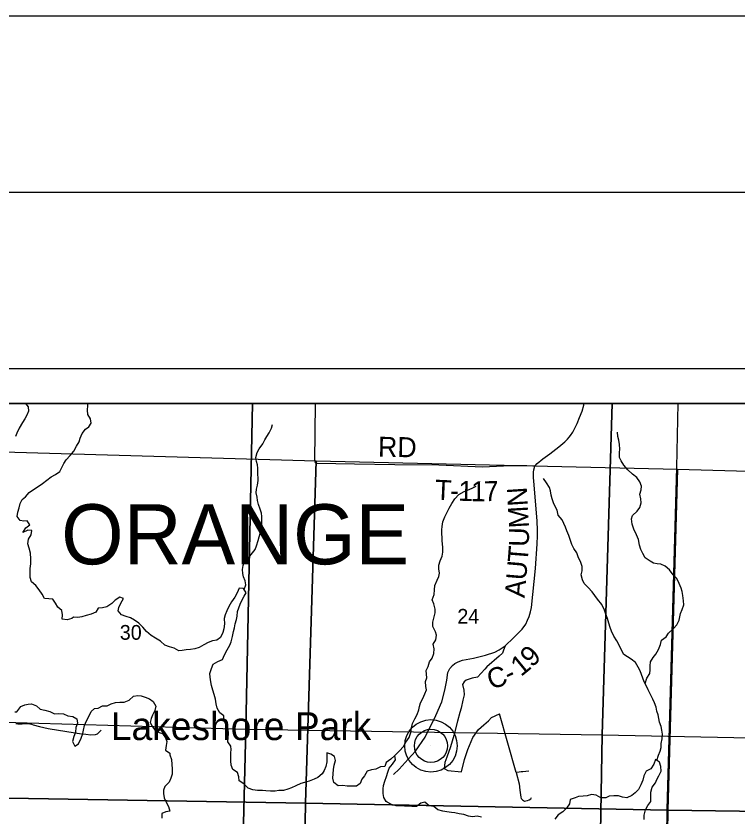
# Model space of a CAD drawing. Extents: x -19.9 to 41.9, y 0 to 32.3.
# Drawn here: x 5.266 to 7.317, y 19.727 to 22 of the extents above; entities that cross this region are included whole.
import ezdxf

# ---------------------------------------------------------------- set-up
doc = ezdxf.new("R2010")
doc.units = 0
for name, color, linetype in [('GM_X_Corporation', 7, 'Continuous'), ('GM_X_County_Road', 7, 'Continuous'), ('GM_X_County_Road_Text', 7, 'Continuous'), ('GM_X_Major_Lake', 7, 'Continuous'), ('GM_X_Minor_River', 7, 'Continuous'), ('GM_X_Section', 7, 'Continuous'), ('GM_X_Section_Text', 7, 'Continuous'), ('GM_X_Township', 7, 'Continuous'), ('GM_X_Township_Road', 7, 'Continuous'), ('GM_X_Township_Road_Text', 7, 'Continuous'), ('GM_X_Township_Text', 7, 'Continuous'), ('GM_X_Unincorporated', 7, 'Continuous'), ('GM_X_Unincorporated_Location', 7, 'Continuous'), ('GM_X_Unincorporated_Text', 7, 'Continuous'), ('SH_Border', 7, 'Continuous'), ('SH_Cut_Line', 7, 'Continuous'), ('SH_Data', 7, 'Continuous')]:
    doc.layers.add(name, color=color, linetype=linetype)

msp = doc.modelspace()

# ---------------------------------------------------------------- linework, layer by layer
at = {"layer": 'GM_X_Corporation'}
for points in [[(8.9, 17.8974), (8.9, 20.9), (2.1, 20.9), (2.1, 17.918), (2.4715, 17.9106), (2.973, 17.9007), (3.7505, 17.884), (3.984, 17.879), (4.2613, 17.8672), (4.9169, 17.8392), (5.0192, 17.8403), (5.0257, 17.9637), (5.4954, 17.9559), (5.761, 17.9543), (5.9048, 17.9534), (6.2397, 17.9517), (6.2497, 17.9517), (6.3069, 17.9505), (6.7, 17.9422), (6.9468, 17.937), (7.3858, 17.9277), (7.5529, 17.9242), (7.9072, 17.9171)], [(5.9372, 20.9), (5.0886, 20.9), (5.0885, 20.8933), (5.0685, 20), (5.9183, 19.976)], [(6.9594, 20.9), (5.9372, 20.9), (5.9183, 19.976), (6.9305, 19.9596)], [(7.9862, 20.9), (6.9594, 20.9), (6.9305, 19.9596), (7.9591, 19.9393)], [(5.0685, 20), (5.9183, 19.976), (5.8941, 18.9811), (5.0551, 18.9965), (5.0703, 19.9026)], [(5.9183, 19.976), (6.9305, 19.9596), (6.9135, 18.9637), (5.8941, 18.9811)], [(7.9591, 19.9393), (7.944, 18.9426), (6.9135, 18.9637), (6.9305, 19.9596)]]:
    msp.add_lwpolyline(points, close=True, dxfattribs=at)
msp.add_lwpolyline([(2.973, 17.9007), (3.7505, 17.884), (3.984, 17.879), (4.2613, 17.8672), (4.9169, 17.8392), (5.0192, 17.8403), (5.0257, 17.9637), (5.4954, 17.9559), (5.761, 17.9543), (5.9048, 17.9534), (6.2397, 17.9517), (6.2497, 17.9517), (6.3069, 17.9505), (6.7, 17.9422), (6.9468, 17.937), (7.3858, 17.9277), (7.5529, 17.9242), (7.9072, 17.9171), (7.9208, 18.3004), (7.9387, 18.9418), (7.9433, 19.1981), (7.9567, 19.9408), (7.9833, 20.9), (2.1, 20.9)], dxfattribs=at)
at = {"layer": 'GM_X_County_Road'}
msp.add_lwpolyline([(6.3377, 19.8473), (6.3538, 19.8624), (6.38, 19.891), (6.401, 19.9134), (6.4282, 19.9531), (6.4584, 20.0142), (6.4757, 20.053), (6.4844, 20.0865), (6.4893, 20.1146), (6.4921, 20.1368), (6.4982, 20.148), (6.5055, 20.157), (6.5124, 20.1627), (6.5214, 20.1674), (6.534, 20.1714), (6.565, 20.177), (6.5993, 20.1859), (6.6261, 20.1947), (6.6385, 20.2011), (6.6466, 20.2068), (6.6551, 20.2126), (6.6791, 20.235), (6.7039, 20.2596), (6.714, 20.2739), (6.719, 20.2853), (6.7234, 20.296), (6.7274, 20.3087), (6.7304, 20.3216), (6.7414, 20.4315), (6.7458, 20.5016), (6.7474, 20.5248), (6.7469, 20.5411), (6.7464, 20.5661), (6.7377, 20.6691), (6.7359, 20.6902), (6.7357, 20.7051), (6.7369, 20.7118), (6.7382, 20.7189), (6.7394, 20.7228), (6.7462, 20.7302), (6.7623, 20.7431), (6.7826, 20.7572), (6.8082, 20.7775), (6.8244, 20.7918), (6.832, 20.7991), (6.837, 20.8048), (6.8409, 20.8095), (6.8477, 20.8185), (6.8534, 20.8305), (6.8594, 20.843), (6.8664, 20.86), (6.8739, 20.8784), (6.8788, 20.8957), (6.8798, 20.9)], dxfattribs=at)
at = {"layer": 'GM_X_Major_Lake'}
for points in [[(5.2926, 20.9), (5.3008, 20.8907), (5.3018, 20.8789), (5.2963, 20.8667), (5.2911, 20.8568), (5.2841, 20.846), (5.2749, 20.8299), (5.2679, 20.8162), (5.2642, 20.8062)], [(5.2832, 20.6279), (5.2929, 20.6356), (5.3034, 20.6476), (5.3184, 20.658), (5.3286, 20.6647), (5.3414, 20.6732), (5.3534, 20.6829), (5.3654, 20.6918), (5.3778, 20.6985), (5.3902, 20.7074), (5.395, 20.717), (5.402, 20.7303), (5.4083, 20.7403), (5.4199, 20.7526), (5.4299, 20.7653), (5.438, 20.7787), (5.4454, 20.791), (5.4483, 20.8017), (5.4538, 20.8147), (5.4635, 20.8273), (5.4732, 20.8336), (5.4795, 20.8443), (5.4774, 20.8571), (5.4696, 20.8692), (5.4686, 20.8809), (5.4699, 20.8942), (5.4698, 20.9)], [(5.4246, 20.2899), (5.4117, 20.2863), (5.3968, 20.2879), (5.3978, 20.3005), (5.3964, 20.3126), (5.3845, 20.3223), (5.3782, 20.3339), (5.3704, 20.3452), (5.359, 20.3461), (5.3468, 20.3471), (5.3398, 20.3587), (5.3316, 20.3711), (5.3219, 20.3838), (5.3095, 20.3939), (5.3059, 20.4067), (5.3057, 20.4204), (5.3066, 20.4321), (5.3079, 20.4451), (5.3084, 20.4591), (5.3074, 20.4758), (5.303, 20.4894), (5.2994, 20.5018), (5.3014, 20.5148), (5.3092, 20.527), (5.3113, 20.5396), (5.2998, 20.5409), (5.2855, 20.5342), (5.2937, 20.5472), (5.3049, 20.5558), (5.2975, 20.5674), (5.288, 20.5665), (5.2781, 20.5679), (5.2696, 20.5795), (5.2712, 20.5916), (5.2745, 20.6038), (5.2777, 20.6164), (5.2832, 20.6279)], [(5.9133, 19.8207), (5.8998, 19.8292), (5.8992, 19.841), (5.8949, 19.8531), (5.8822, 19.8616), (5.8774, 19.874), (5.8761, 19.8857), (5.8759, 19.8979), (5.8761, 19.9085), (5.8771, 19.918), (5.8761, 19.9279), (5.868, 19.9395), (5.8681, 19.9512), (5.8698, 19.9638), (5.8681, 19.9767), (5.8626, 19.988), (5.8559, 20.0011), (5.8565, 20.0136), (5.8445, 20.0226), (5.8371, 20.0357), (5.8342, 20.0478), (5.8325, 20.0607), (5.8288, 20.0739), (5.8248, 20.0863), (5.8216, 20.0999), (5.8195, 20.1098), (5.817, 20.1234), (5.8168, 20.134), (5.8211, 20.1477), (5.8263, 20.1603), (5.839, 20.1681), (5.8523, 20.1737), (5.8581, 20.1867), (5.8655, 20.2008), (5.8736, 20.2138), (5.8773, 20.2238), (5.8812, 20.239), (5.8836, 20.2527), (5.8861, 20.2637), (5.8886, 20.2744), (5.8922, 20.287), (5.8939, 20.2965), (5.8952, 20.3098), (5.8985, 20.3201), (5.9025, 20.3308), (5.9073, 20.3407), (5.9143, 20.3534), (5.9194, 20.3629), (5.9124, 20.3749), (5.8998, 20.3759), (5.894, 20.3625), (5.8877, 20.3503), (5.878, 20.3368), (5.8703, 20.3242), (5.8644, 20.3119), (5.8597, 20.3001), (5.8575, 20.2902), (5.8578, 20.275), (5.8561, 20.2602), (5.8533, 20.2499), (5.8467, 20.2362), (5.8365, 20.2288), (5.8236, 20.2267), (5.8115, 20.2219), (5.7995, 20.2149), (5.7863, 20.2075), (5.7742, 20.2035), (5.7613, 20.2018), (5.7492, 20.2008), (5.7378, 20.1991), (5.7283, 20.1986), (5.7153, 20.2055), (5.7015, 20.2095), (5.6889, 20.2142), (5.6761, 20.2254), (5.6623, 20.2339), (5.6497, 20.2413), (5.6369, 20.2528), (5.6261, 20.2652), (5.6152, 20.2764), (5.6025, 20.2856), (5.591, 20.2919), (5.5784, 20.2955), (5.5654, 20.3006), (5.5565, 20.3114), (5.5578, 20.3209), (5.5637, 20.3339), (5.5711, 20.347), (5.5612, 20.3506), (5.5476, 20.342), (5.5379, 20.3327), (5.524, 20.3234), (5.5115, 20.3206), (5.4997, 20.3196), (5.4923, 20.3081), (5.4795, 20.3018), (5.4655, 20.2989), (5.4526, 20.2949), (5.4412, 20.2928), (5.429, 20.2942), (5.4246, 20.2899)], [(5.2624, 20.0255), (5.2682, 20.0252), (5.2797, 20.0398), (5.2914, 20.0449), (5.3009, 20.0466), (5.3104, 20.0475), (5.3238, 20.0421), (5.3346, 20.0324), (5.3483, 20.0296), (5.3617, 20.0256), (5.3751, 20.0198), (5.3876, 20.02), (5.4009, 20.019), (5.4132, 20.0136), (5.4269, 20.0115), (5.4388, 20.0052), (5.4409, 19.9931), (5.4362, 19.9802), (5.4345, 19.9676), (5.4305, 19.9547), (5.4266, 19.9409), (5.4329, 19.9278), (5.4434, 19.9344), (5.4511, 19.9504), (5.4562, 19.9638), (5.458, 19.9733), (5.4608, 19.9859), (5.4659, 19.9996), (5.4725, 20.0119), (5.4791, 20.0264), (5.4889, 20.0341), (5.4991, 20.0355), (5.5116, 20.0421), (5.5249, 20.0423), (5.5365, 20.0482), (5.5487, 20.0518), (5.5604, 20.0524), (5.5734, 20.0522), (5.5873, 20.0585), (5.5997, 20.0697), (5.6118, 20.0711), (5.6213, 20.0701), (5.6332, 20.0665), (5.645, 20.0621), (5.6551, 20.054), (5.6629, 20.0416), (5.66, 20.0286), (5.6538, 20.016), (5.6494, 20.0061), (5.6469, 19.9946), (5.6528, 19.9841)], [(5.6528, 19.9841), (5.661, 19.9725), (5.6721, 19.9666), (5.6817, 19.9637), (5.6906, 19.951), (5.6942, 19.9412), (5.6921, 19.9298), (5.6904, 19.9164), (5.7024, 19.9075)], [(5.7024, 19.9075), (5.7032, 19.9026), (5.7072, 19.8898), (5.709, 19.8754), (5.7096, 19.8629), (5.7094, 19.8485), (5.7058, 19.8367), (5.7007, 19.8252), (5.6883, 19.8132), (5.6847, 19.8029), (5.6853, 19.7934), (5.687, 19.7806), (5.6921, 19.7689), (5.6992, 19.7561), (5.7032, 19.7433), (5.6911, 19.7412), (5.6801, 19.7361), (5.6803, 19.7232)], [(6.3175, 19.7702), (6.3108, 19.7822), (6.3087, 19.7931), (6.3089, 19.8068), (6.3098, 19.8163), (6.3138, 19.8285), (6.3182, 19.8415), (6.3225, 19.8541), (6.3258, 19.8655), (6.3354, 19.8767), (6.344, 19.8886), (6.3423, 19.9011), (6.3306, 19.891), (6.3175, 19.8813), (6.3139, 19.8702), (6.301, 19.8685), (6.2882, 19.8626), (6.276, 19.8605), (6.2635, 19.8569), (6.2562, 19.8431), (6.248, 19.8335), (6.2436, 19.822), (6.2327, 19.8143), (6.2202, 19.8137), (6.2061, 19.8142), (6.1943, 19.8155), (6.1814, 19.8153), (6.1687, 19.8242), (6.1658, 19.8367), (6.1664, 19.8488), (6.168, 19.8618), (6.1701, 19.8739), (6.173, 19.8869), (6.1709, 19.8982), (6.1597, 19.9045), (6.149, 19.9089), (6.1485, 19.8956), (6.1487, 19.8827), (6.1455, 19.8697), (6.1411, 19.859), (6.1352, 19.8491), (6.1236, 19.8383), (6.1126, 19.8339), (6.099, 19.8287), (6.085, 19.824), (6.0752, 19.8215), (6.0612, 19.8148), (6.048, 19.8093), (6.0382, 19.8057), (6.0253, 19.8021), (6.012, 19.8015), (6.0022, 19.8002), (5.9885, 19.8), (5.9759, 19.8009), (5.9664, 19.8015), (5.952, 19.8016), (5.939, 19.8033), (5.9256, 19.8088), (5.9133, 19.8207)], [(7.0497, 19.7194), (7.0499, 19.7319), (7.0538, 19.7468), (7.0608, 19.759), (7.0694, 19.7709), (7.0692, 19.7846), (7.0686, 19.7975), (7.0733, 19.8108), (7.0822, 19.8239), (7.0862, 19.8334), (7.0914, 19.843), (7.0984, 19.8568), (7.0978, 19.8697), (7.0934, 19.8825), (7.0826, 19.8895), (7.0779, 19.8765), (7.0686, 19.8635), (7.0562, 19.8565), (7.0488, 19.8434), (7.046, 19.8309), (7.0405, 19.8175), (7.0338, 19.8049), (7.0245, 19.7948), (7.0147, 19.7875), (7.0012, 19.7812), (6.989, 19.7829), (6.9775, 19.7869), (6.9638, 19.787), (6.9509, 19.7853), (6.9411, 19.7809), (6.9274, 19.7807), (6.914, 19.7884), (6.9007, 19.7901), (6.8878, 19.7869), (6.8772, 19.7859), (6.8635, 19.7846), (6.8537, 19.7814), (6.8404, 19.7762), (6.8376, 19.7637), (6.8291, 19.7517), (6.819, 19.7413), (6.8058, 19.7324), (6.7961, 19.7201)], [(6.5881, 19.7257), (6.5759, 19.7293), (6.563, 19.7272), (6.5515, 19.7293), (6.5378, 19.7332), (6.5248, 19.736), (6.5122, 19.7385), (6.5027, 19.7395), (6.4901, 19.7412), (6.4779, 19.7432), (6.4642, 19.7468), (6.4523, 19.7565), (6.4393, 19.7578), (6.4273, 19.7689), (6.4156, 19.7657), (6.4036, 19.756), (6.3907, 19.7566), (6.3785, 19.7571), (6.369, 19.757), (6.3595, 19.758), (6.3462, 19.7581), (6.3328, 19.7617), (6.3201, 19.7691), (6.3175, 19.7702)]]:
    msp.add_lwpolyline(points, dxfattribs=at)
at = {"layer": 'GM_X_Minor_River'}
for points in [[(5.9137, 20.3727), (5.9183, 20.3859), (5.9167, 20.3969), (5.9121, 20.4078), (5.9101, 20.4181), (5.9092, 20.4294), (5.911, 20.4405), (5.9144, 20.4507), (5.9249, 20.4603), (5.9343, 20.4718), (5.9452, 20.4859), (5.9489, 20.4958), (5.9537, 20.5114), (5.957, 20.522), (5.9603, 20.5338), (5.964, 20.5464), (5.9643, 20.5559), (5.9641, 20.579), (5.9633, 20.5892), (5.9598, 20.6006), (5.9551, 20.6134), (5.9519, 20.6252), (5.9507, 20.6346), (5.9483, 20.6464), (5.949, 20.657), (5.9519, 20.6684), (5.9533, 20.6817), (5.9531, 20.706), (5.9527, 20.7162), (5.9518, 20.7257), (5.9487, 20.7359), (5.9471, 20.7465), (5.9507, 20.7613), (5.9564, 20.7713), (5.9669, 20.7861), (5.9725, 20.7968), (5.9788, 20.8063), (5.9852, 20.8166), (5.9919, 20.83), (5.9949, 20.841)], [(7.0525, 20.1053), (7.0576, 20.1203), (7.0658, 20.1336), (7.0676, 20.1442), (7.0668, 20.1552), (7.0678, 20.167), (7.0757, 20.1788), (7.0832, 20.1888), (7.0907, 20.2021), (7.0962, 20.2162), (7.0992, 20.2284), (7.1128, 20.2383), (7.1188, 20.2482), (7.1334, 20.2617), (7.1432, 20.2716), (7.15, 20.2849), (7.1518, 20.2944), (7.1532, 20.3043), (7.158, 20.3157), (7.1625, 20.329), (7.1616, 20.3404), (7.16, 20.3556), (7.1584, 20.3662), (7.1552, 20.3764), (7.1494, 20.3896), (7.1425, 20.4036), (7.1329, 20.4141), (7.1217, 20.4277), (7.1099, 20.4386), (7.0977, 20.4442), (7.0874, 20.4452), (7.0771, 20.4474), (7.0668, 20.4526), (7.0534, 20.4624), (7.0461, 20.4748), (7.0407, 20.4858), (7.0368, 20.4983), (7.0336, 20.5146), (7.0285, 20.5278), (7.0208, 20.5437), (7.0157, 20.558), (7.0141, 20.5724), (7.017, 20.5819), (7.0302, 20.5946), (7.0381, 20.6053), (7.0414, 20.6186), (7.0409, 20.6296), (7.0382, 20.6432), (7.0415, 20.655), (7.0421, 20.6652), (7.0382, 20.6777), (7.029, 20.6898), (7.0168, 20.6992), (7.0037, 20.7123), (6.9926, 20.7247), (6.9849, 20.7376), (6.9803, 20.7474), (6.9805, 20.7614), (6.9812, 20.7709), (6.9803, 20.7838), (6.9783, 20.7963), (6.9756, 20.8062), (6.9743, 20.8187)], [(6.3423, 19.9011), (6.3548, 19.9143), (6.3668, 19.9269), (6.3728, 19.9387), (6.3822, 19.9524), (6.387, 19.9665), (6.3891, 19.9794), (6.3925, 19.992), (6.3992, 20.0053), (6.4051, 20.0179), (6.41, 20.0308), (6.4118, 20.0403), (6.4144, 20.0502), (6.4218, 20.0632), (6.4274, 20.0757), (6.4315, 20.0872), (6.4303, 20.097), (6.4294, 20.1107), (6.4327, 20.1213), (6.4315, 20.1315), (6.431, 20.1422), (6.437, 20.154), (6.4407, 20.1673), (6.4482, 20.1776), (6.4526, 20.1905), (6.4533, 20.2038), (6.4505, 20.2167), (6.4587, 20.2297), (6.4601, 20.2426), (6.4578, 20.2524), (6.4501, 20.2671), (6.4503, 20.2793), (6.454, 20.2949), (6.4565, 20.3063), (6.4568, 20.3165), (6.4525, 20.3316), (6.4482, 20.343), (6.4538, 20.3582), (6.4545, 20.3715), (6.4555, 20.3833), (6.4622, 20.3989), (6.4667, 20.4088), (6.4692, 20.419), (6.4672, 20.4308), (6.4667, 20.4418), (6.4708, 20.4536), (6.4764, 20.4665), (6.4782, 20.4787), (6.4785, 20.4923), (6.4764, 20.5101), (6.4763, 20.52), (6.4751, 20.5302), (6.475, 20.5416), (6.476, 20.5511), (6.4786, 20.564), (6.4842, 20.5781), (6.4901, 20.5903), (6.4961, 20.6029), (6.5036, 20.6166), (6.5122, 20.6296), (6.5235, 20.6418), (6.539, 20.6507), (6.5526, 20.6557), (6.5632, 20.6604), (6.573, 20.6654)], [(7.0862, 19.8872), (7.091, 19.9017), (7.0951, 19.9138), (7.0984, 19.9237), (7.0987, 19.9351), (7.1013, 19.948), (7.1023, 19.9613), (7.1007, 19.9731), (7.0983, 19.9833), (7.094, 19.9954), (7.0916, 20.006), (7.0896, 20.0162), (7.0865, 20.0272), (7.0845, 20.0382), (7.0795, 20.051), (7.0744, 20.0608), (7.0679, 20.0744), (7.0613, 20.0877), (7.0563, 20.0975), (7.0501, 20.1103), (7.0466, 20.1205), (7.0427, 20.1311), (7.0384, 20.1413), (7.033, 20.1515), (7.0257, 20.1647), (7.013, 20.1745), (7.0024, 20.1809), (6.9928, 20.1876), (6.9839, 20.2035), (6.9789, 20.214), (6.9727, 20.2261), (6.9638, 20.2401), (6.9573, 20.2544), (6.9534, 20.2646), (6.9502, 20.2764), (6.9459, 20.2904), (6.9409, 20.3025), (6.9374, 20.3134), (6.9296, 20.3297), (6.9177, 20.3448), (6.9097, 20.3553), (6.9023, 20.3655), (6.8908, 20.3779), (6.8797, 20.3892), (6.8747, 20.3994), (6.8708, 20.4138), (6.8737, 20.4256), (6.8736, 20.4377), (6.8689, 20.4517), (6.8639, 20.4619), (6.8588, 20.4763), (6.8504, 20.4887), (6.8446, 20.5004), (6.8395, 20.5144), (6.836, 20.5254), (6.8305, 20.5386), (6.827, 20.5488), (6.8224, 20.5594), (6.817, 20.5696), (6.8055, 20.5832), (6.8031, 20.5972), (6.7973, 20.6074), (6.793, 20.6179), (6.7887, 20.6293), (6.786, 20.6399), (6.784, 20.652), (6.7812, 20.6618), (6.7727, 20.6754), (6.7639, 20.6871)]]:
    msp.add_lwpolyline(points, dxfattribs=at)
at = {"layer": 'GM_X_Section'}
for points in [[(5.0965, 20.7671), (6.1184, 20.7376), (6.0885, 19.7661), (5.0763, 19.7825)], [(6.1184, 20.7376), (7.1444, 20.7139), (7.1171, 19.7458), (6.0885, 19.7661)], [(7.1444, 20.7139), (8.1526, 20.6857), (8.1335, 19.7322), (7.1171, 19.7458)], [(5.0763, 19.7825), (6.0885, 19.7661), (6.0716, 18.7702), (5.0521, 18.7876)], [(7.1171, 19.7458), (7.1021, 18.7492), (6.0716, 18.7702), (6.0885, 19.7661)], [(7.1171, 19.7458), (8.1335, 19.7322), (8.1079, 18.7263), (7.1021, 18.7492)]]:
    msp.add_lwpolyline(points, close=True, dxfattribs=at)
at = {"layer": 'GM_X_Township'}
for p, q in [((7.1461, 20.9), (7.1416, 20.7181)), ((7.1416, 20.7181), (7.1147, 19.7474)), ((7.1147, 19.7474), (7.1013, 19.0046))]:
    msp.add_line(p, q, dxfattribs=at)
at = {"layer": 'GM_X_Township_Road'}
for points in [[(6.7394, 20.7228), (6.7173, 20.7237), (6.6701, 20.7237), (6.591, 20.7195), (6.4667, 20.7253), (6.342, 20.7258), (6.2272, 20.7281), (6.1213, 20.7303), (6.1197, 20.7309), (6.1179, 20.7321), (6.1159, 20.7345), (6.1151, 20.7366), (6.1163, 20.9)], [(6.6551, 20.2126), (6.6505, 20.2004), (6.6479, 20.1911), (6.6386, 20.1828), (6.6033, 20.1524), (6.5971, 20.1457)], [(6.5971, 20.1457), (6.5767, 20.1235), (6.5612, 20.1208), (6.5441, 20.1152), (6.5385, 20.1103), (6.5346, 20.1028), (6.5376, 20.0866), (6.5389, 20.0732), (6.5349, 20.0577), (6.5303, 20.035), (6.527, 20.0236)], [(6.527, 20.0236), (6.5195, 19.9982), (6.5093, 19.9577), (6.4997, 19.9259), (6.4899, 19.8959), (6.4843, 19.8808), (6.482, 19.8644), (6.4922, 19.8588), (6.531, 19.8548)], [(6.531, 19.8548), (6.5399, 19.8894), (6.5497, 19.9183), (6.5632, 19.9518), (6.58, 19.9748), (6.5944, 19.9877), (6.6079, 19.9995), (6.6165, 20.009), (6.6395, 20.0192)], [(6.723, 19.8571), (6.7059, 19.8552), (6.701, 19.8545), (6.6947, 19.8535), (6.6868, 19.8525), (6.6395, 20.0192)], [(5.2655, 19.9921), (5.2709, 19.9911), (5.2833, 19.9909), (5.2962, 19.9917), (5.3008, 19.9916), (5.305, 19.991), (5.3095, 19.9899), (5.3151, 19.9882), (5.3329, 19.9832), (5.357, 19.9778), (5.4341, 19.9655), (5.4518, 19.9623), (5.4645, 19.9612), (5.4783, 19.9602), (5.4913, 19.961), (5.4972, 19.9623), (5.5082, 19.9726)], [(6.6868, 19.8525), (6.6951, 19.8203), (6.6974, 19.8026), (6.6985, 19.7896), (6.6995, 19.7827), (6.7005, 19.779), (6.7048, 19.7748), (6.7104, 19.7718), (6.7138, 19.7728), (6.7186, 19.7733), (6.7238, 19.7753), (6.7278, 19.7784), (6.7304, 19.7815)]]:
    msp.add_lwpolyline(points, dxfattribs=at)
at = {"layer": 'GM_X_Unincorporated'}
for radius in [0.0744, 0.0472]:
    msp.add_circle((6.4446, 19.9285), radius, dxfattribs=at)
at = {"layer": 'GM_X_Unincorporated_Location'}
msp.add_line((6.4446, 19.9285), (6.4446, 19.9285), dxfattribs=at)
at = {"layer": 'SH_Border'}
msp.add_lwpolyline([(1.5, 21.5), (33.5, 21.5), (33.5, 0.5), (1.5, 0.5)], close=True, dxfattribs=at)
at = {"layer": 'SH_Cut_Line'}
msp.add_lwpolyline([(0, 0), (34, 0), (34, 22), (0, 22)], close=True, dxfattribs=at)
at = {"layer": 'SH_Data'}
for p, q in [((2, 21), (9, 21)), ((2.1, 20.9), (8.9, 20.9))]:
    msp.add_line(p, q, dxfattribs=at)

# ---------------------------------------------------------------- texts
at = {"layer": 'GM_X_County_Road_Text'}
for s, rotation, p in [('N', 93.7532, (6.7199, 20.6101)), ('M', 93.2844, (6.7234, 20.548)), ('U', 88.7388, (6.7224, 20.4931)), ('T', 85.4755, (6.7189, 20.4472)), ('U', 85.2261, (6.7147, 20.3971)), ('A', 85.2297, (6.7106, 20.3473)), ('9', 44.1561, (6.7312, 20.149)), ('1', 39.3224, (6.7002, 20.1233)), ('C', 17.687, (6.6144, 20.0878)), ('-', 26.0766, (6.6672, 20.1053))]:
    msp.add_text(s, height=0.0568, rotation=rotation, dxfattribs=at).set_placement(p)
at = {"layer": 'GM_X_Section_Text'}
for s, p in [('24', (6.5195, 20.2753)), ('30', (5.5607, 20.2296))]:
    msp.add_text(s, height=0.04186, rotation=0, dxfattribs=at).set_placement(p)
at = {"layer": 'GM_X_Township_Road_Text'}
for s, height, rotation, p in [('RD', 0.05682, 359.0293, (6.2938, 20.7491)), ('T', 0.0568, 357.4727, (6.4551, 20.6273)), ('1', 0.0568, 357.9312, (6.5214, 20.6244)), ('1', 0.0568, 358.9515, (6.5575, 20.6231)), ('7', 0.0568, 1.7317, (6.5955, 20.6225)), ('-', 0.0568, 357.5755, (6.4977, 20.6254))]:
    msp.add_text(s, height=height, rotation=rotation, dxfattribs=at).set_placement(p)
at = {"layer": 'GM_X_Township_Text'}
msp.add_text('ORANGE', height=0.17045, rotation=0, dxfattribs=at).set_placement((5.3944, 20.4437))
at = {"layer": 'GM_X_Unincorporated_Text'}
msp.add_text('Lakeshore Park', height=0.078977, rotation=0, dxfattribs=at).set_placement((5.5353, 19.9449))

doc.saveas('drawing.dxf')
